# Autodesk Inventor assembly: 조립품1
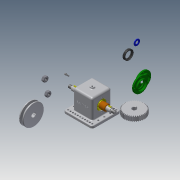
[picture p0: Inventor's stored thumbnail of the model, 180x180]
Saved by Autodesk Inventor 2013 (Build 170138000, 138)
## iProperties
Created: 2018-11
Part Number: 조립품1
Document SubType Name: Assembly
Designer: Administrator
Author: Administrator
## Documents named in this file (13)
- C:\Users\Administrator\Desktop\481107V1030\조립품1.iam
- C:\Users\Administrator\Desktop\481107V1030\본체.ipt
- C:\Users\Administrator\Desktop\481107V1030\V벨트풀리.ipt
- C:\Users\Administrator\Desktop\481107V1030\너트 M12x1.25.ipt
- C:\Users\Administrator\Desktop\481107V1030\베어링 6203.ipt
- C:\Users\Administrator\Desktop\481107V1030\볼트 M4.ipt
- C:\Users\Administrator\Desktop\481107V1030\부시.ipt
- C:\Users\Administrator\Desktop\481107V1030\스퍼기어.ipt
- C:\Users\Administrator\Desktop\481107V1030\오일 실 26 38 8.ipt
- C:\Users\Administrator\Desktop\481107V1030\와셔 12x24.ipt
- C:\Users\Administrator\Desktop\481107V1030\축.ipt
- C:\Users\Administrator\Desktop\481107V1030\커버.ipt
- C:\Users\Administrator\Desktop\481107V1030\키 5x5x12.ipt
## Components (1 placed, 1 different names)
1. V벨트풀리:1
